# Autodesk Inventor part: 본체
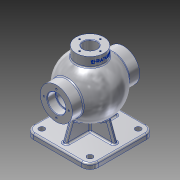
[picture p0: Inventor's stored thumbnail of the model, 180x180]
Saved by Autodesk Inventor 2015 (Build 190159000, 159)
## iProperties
Created: 2025-08
Part Number: 본체
Material: 알루미늄 6061
Document SubType Name: Modeling
Designer: user
Density: 2.7 g/cm^3
Appearance: 알루미늄 - 평지
Mass: 1526.72 g
Surface Area: 1173.82 cm^2
Volume: 565.453 cm^3
Author: user
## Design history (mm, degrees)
sketch "스케치1"
  geometry: L1 (-46.5, 62.5)-(46.5, 62.5); L2 (62.5, 46.5)-(62.5, -46.5); L3 (46.5, -62.5)-(-46.5, -62.5); L4 (-62.5, -46.5)-(-62.5, 46.5); A1 r 16 centre (-46.5, 46.5) between (-46.5, 62.5) and (-62.5, 46.5); A2 r 16 centre (46.5, 46.5) between (62.5, 46.5) and (46.5, 62.5); A3 r 16 centre (46.5, -46.5) between (46.5, -62.5) and (62.5, -46.5); A4 r 16 centre (-46.5, -46.5) between (-62.5, -46.5) and (-46.5, -62.5); 4 further points
  constraints: 8 end point, 8 point on circle, 8 tangent, 6 point on line, 4 centre point, 2 parallel, 1 horizontal, 1 perpendicular
  dimensions: "d0" = 125 distance of point (-62.5, 62.5) point (62.5, 62.5); "d1" = 125 distance of point (62.5, 62.5) point (62.5, -62.5); "d2" = 62.5 distance from line of L1 point (0, 0); "d3" = 62.5 distance from line of L2 point (0, 0); "d4" = 16 radius of A1; "d5" = 16 radius of A2; "d6" = 16 radius of A3; "d7" = 16 radius of A4
extrude "돌출1" new body sketch "스케치1" distance "d8" = 10; taper "d9" = 0 deg
hole "구멍1" diameter "d12" = 11; stored, may be unused: countersink angle "d16" = 90 deg, drill point angle "d18" = 118 deg; dims "d10" = 16, "d11" = 16, "d13" = 6, "d14" = 4, "d15" = 2, "d17" = 8
sketch "스케치3"
  geometry: L1 (62.5, 10)-(62.5, 0) reference; L2 (62.5, 0)-(-62.5, 0) reference; L3 (-62.5, 0)-(-62.5, 10) reference; L4 (-62.5, 10)-(62.5, 10) reference; L5 (41, 10)-(52, 10) reference; L6 (50.5, 10)-(28.392, 70.741); L7 (28.392, 70.741)-(-28.392, 70.741); L8 (-28.392, 70.741)-(-50.5, 10); L9 (-46.5, 10)-(-62.5, 10) reference; 1 further point
  constraints: 6 end point, 2 point on line, 1 parallel
  dimensions: "d25" = 20 deg angle of L3 L8; "d26" = 20 deg angle of L1 L6; "d27" = 12 distance of L3.end L8.end; "d28" = 12 distance of L6.start L1.start; "d29" = 56.78418 distance of L6.end L7.end
extrude "돌출2" join sketch "스케치3" stored distance "d30" = 8; taper "d31" = 0 deg
sketch "스케치4"
  geometry: L1 (62.5, 10)-(62.5, 0) reference; L2 (62.5, 0)-(-62.5, 0) reference; L3 (-62.5, 0)-(-62.5, 10) reference; L4 (-62.5, 10)-(-4, 10) reference; L5 (-4, 10)-(-4, 70.741) reference; L6 (-4, 70.741)-(4, 70.741) reference; L7 (4, 70.741)-(4, 10) reference; L8 (4, 10)-(62.5, 10) reference; L9 (-52, 10)-(-41, 10) reference; L10 (-46.5, 10)-(-62.5, 10) reference; L11 (-50.5, 10)-(-29.534, 67.603); L12 (-29.534, 67.603)-(29.534, 67.603); L13 (29.534, 67.603)-(50.5, 10); L14 (62.5, 10)-(46.5, 10) reference; 1 further point
  constraints: 6 end point, 2 point on line, 1 parallel
  dimensions: "d32" = 12 distance of L11.start L3.end; "d33" = 12 distance of L1.start L13.end; "d34" = 20 deg angle of L1 L13; "d35" = 20 deg angle of L3 L11; "d36" = 59.06819 distance of L11.end L12.end
extrude "돌출3" join sketch "스케치4" stored distance "d37" = 8; taper "d38" = 0 deg
sketch "스케치6"
  geometry: L1 (0, 139)-(0, 31); L2 (-4, 10)-(-4, 67.603) reference; L3 (-46.5, 0)-(46.5, 0) reference; A1 r 54 centre (0, 85) between (0, 139) and (0, 31); A2 r 44 centre (0, 85) between (0, 129) and (0, 41); 3 further points
  constraints: 4 point on circle, 2 centre point, 2 coincident, 2 end point, 2 midpoint, 2 point on line, 1 parallel, 1 vertical alignment
  dimensions: "d42" = 108 diameter of A1; "d44" = 88 diameter of A2; "d50" = 85 distance from line of A1.centre L3
revolve "회전2" sketch "스케치6" stored, may be unused: angle "d45" = 90 deg
node "작업 평면1"
sketch "스케치8"
  geometry: C1 r 27 at (0, 0); 1 further point
  constraints: 1 centre point, 1 coincident
  dimensions: "d51" = 54 diameter of C1
extrude "돌출5" join sketch "스케치8" stored distance "d52" = 130; taper "d53" = 0 deg
node "작업 평면2"
sketch "스케치9"
  geometry: L1 (-46.5, 0)-(46.5, 0) reference; C1 r 31 at (0, 85); 2 further points
  constraints: 1 centre point, 1 midpoint, 1 vertical alignment
  dimensions: "d55" = 62 diameter of C1; "d56" = 85 distance from line of C1.centre L1
extrude "돌출6" join sketch "스케치9" distance "d57" = 130; taper "d58" = 0 deg
sketch "스케치10"
  geometry: L1 (27.526, 70.741)-(28.392, 70.741) reference; L2 (28.392, 70.741)-(33.559, 56.544) reference; L3 (-33.559, 56.544)-(-28.392, 70.741) reference; L4 (-28.392, 70.741)-(-27.526, 70.741) reference; L5 (-27, 150)-(27, 150) reference; L6 (27, 150)-(27, 131.765) reference; L7 (37.385, 46.034)-(50.5, 10) reference; L8 (50.5, 10)-(62.5, 10) reference; L9 (62.5, 10)-(62.5, 0) reference; L10 (62.5, 0)-(-62.5, 0) reference; L11 (-62.5, 0)-(-62.5, 10) reference; L12 (-62.5, 10)-(-50.5, 10) reference; L13 (-50.5, 10)-(-37.385, 46.034) reference; L14 (-27, 131.765)-(-27, 150) reference; L15 (-4, 41.365)-(-4, 54.259) reference; L16 (0, 129)-(0, 41); A1 r 31 centre (0, 85) between (27.526, 70.741) and (-27.526, 70.741) reference; A2 r 44 centre (0, 85) between (33.559, 56.544) and (0, 129) reference; A3 r 44 centre (0, 85) between (0, 129) and (-33.559, 56.544) reference; A4 r 54 centre (0, 85) between (37.385, 46.034) and (27, 131.765) reference; A5 r 54 centre (0, 85) between (-27, 131.765) and (-37.385, 46.034) reference; A6 r 44 centre (0, 85) between (0, 129) and (0, 41); 1 further point
  constraints: 3 end point, 3 point on circle, 1 centre point, 1 coincident, 1 vertical
  dimensions: "d60" = 88 distance of L16.start L16.end
revolve "회전3" sketch "스케치10" stored, may be unused: angle "d61" = 90 deg
hole "구멍2" diameter "d64" = 11; stored, may be unused: countersink angle "d68" = 90 deg, drill point angle "d70" = 118 deg; dims "d62" = 10, "d63" = 10, "d65" = 6, "d66" = 35, "d67" = 16, "d69" = 8
hole "구멍3" diameter "d73" = 30; stored, may be unused: countersink angle "d77" = 90 deg, drill point angle "d79" = 118 deg; dims "d71" = 10, "d72" = 10, "d74" = 6, "d75" = 35, "d76" = 16, "d78" = 8
hole "구멍4" diameter "d82" = 26; stored, may be unused: countersink angle "d86" = 90 deg, drill point angle "d88" = 0 deg; dims "d80" = 10, "d81" = 10, "d83" = 6, "d84" = 26, "d85" = 16, "d87" = 54
sketch "스케치11"
  geometry: L1 (0, 0)-(0, 24); C1 r 17.5 at (0, 0) reference; 1 further point
  constraints: 2 end point, 1 vertical
  dimensions: "d89" = 24 distance of L1.start L1.end
hole "구멍5" sketch "스케치11" at (0, 24) diameter "d90" = 3.242; stored, may be unused: countersink angle "d94" = 90 deg, drill point angle "d96" = 118 deg; dims "d91" = 12, "d92" = 26, "d93" = 16, "d95" = 15
sketch "스케치12"
  geometry: L1 (0, 0)-(0, 20)
  constraints: 2 end point, 1 vertical
  dimensions: "d100" = 20 distance of L1.start L1.end
hole "구멍6" sketch "스케치12" at (0, 20) diameter "d101" = 3.242; stored, may be unused: countersink angle "d105" = 90 deg, drill point angle "d107" = 118 deg; dims "d102" = 9, "d103" = 26, "d104" = 16, "d106" = 11
fillet "모깎기1" dims "d111" = 0.6
chamfer "모따기1" distance "d112" = 1; stored, may be unused: second distance "d113" = 2, angle "d114" = 45 deg
chamfer "모따기2" distance "d115" = 1; stored, may be unused: second distance "d116" = 2, angle "d117" = 45 deg
fillet "모깎기2" dims "d118" = 3
fillet "모깎기3" dims "d119" = 3
fillet "모깎기4" dims "d120" = 3
fillet "모깎기5" dims "d121" = 3
sketch "스케치13"
  geometry: L1 (18.379, 150)-(21.621, 150) reference; 2 further points
  constraints: 1 vertical alignment, 1 other
  dimensions: "d122" = 9 distance from line of point (0, 141) L1
feature "엠보싱1" sketch "스케치13" dims "d0" = 125, "d1" = 125, "d2" = 62.5, "d3" = 62.5, "d4" = 16, "d5" = 16, "d6" = 16, "d7" = 16, "d123" = 0.5, "d124" = 0
sketch "스케치14"
  geometry: 1 further point
node "솔리드1"
pattern_linear "직사각형 패턴1" dims "d21" = 93, "d24" = 93
pattern_circular "원형 패턴1" dims angle "d98" = 360 deg
mirror "대칭1"
pattern_circular "원형 패턴2" dims angle "d109" = 360 deg
node "절단 모서리 투영1"
node "절단 모서리 투영2"
node "절단 모서리 투영5"
other parameters: "d54" = -65
